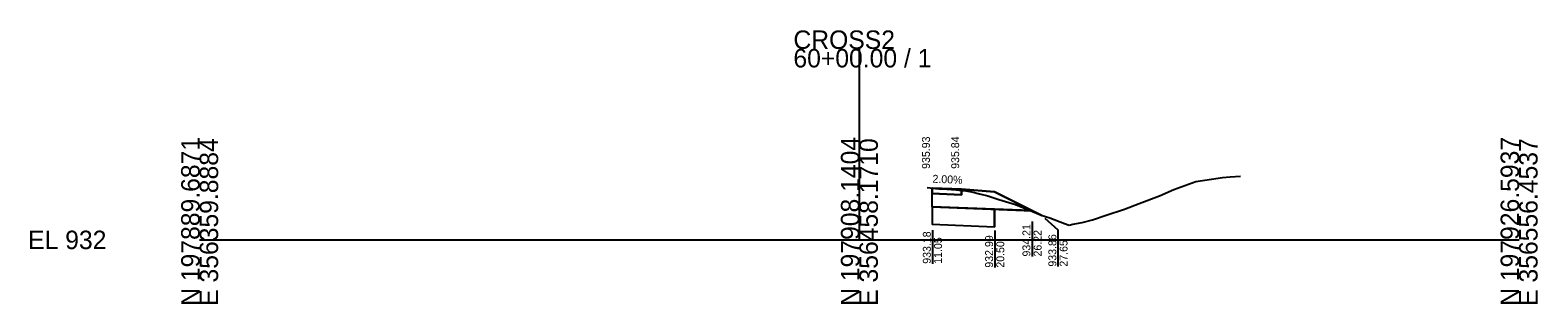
# Model space of a CAD drawing. Extents: x -26 to 203, y -10 to 14021.
# Drawn here: x -25.7 to 202.8, y 990.3 to 1031.8 of the extents above; entities that cross this region are included whole.
import ezdxf

# ---------------------------------------------------------------- set-up
doc = ezdxf.new("R2010")
doc.units = 0
for name, color, linetype in [('Default', 7, 'Continuous'), ('P_E_XS_Ground', 7, 'Continuous'), ('P_XS', 7, 'Continuous'), ('P_XS_EAR_CommonGrnd', 7, 'Continuous'), ('P_XS_Lane', 7, 'Continuous'), ('P_XS_Rock', 7, 'Continuous')]:
    doc.layers.add(name, color=color, linetype=linetype)

msp = doc.modelspace()

# ---------------------------------------------------------------- linework, layer by layer
at = {"layer": 'Default'}
for p, q in [((100, 1000), (100, 1028.94)), ((0, 1000), (100, 1000)), ((100, 1000), (200, 1000))]:
    msp.add_line(p, q, dxfattribs=at)
at = {"layer": 'P_E_XS_Ground'}
for p, q in [((110.28, 1007.95), (112.04, 1007.76)), ((147.68, 1007.65), (151, 1008.87)), ((151, 1008.87), (153.37, 1009.22)), ((153.37, 1009.22), (155.06, 1009.47)), ((155.06, 1009.47), (156.19, 1009.56)), ((156.19, 1009.56), (157.78, 1009.65)), ((112.04, 1007.76), (113.28, 1007.7)), ((113.28, 1007.7), (114.69, 1007.61)), ((114.69, 1007.61), (116.16, 1007.42)), ((116.16, 1007.42), (117.03, 1007.28)), ((117.03, 1007.28), (118.22, 1006.99)), ((118.22, 1006.99), (119.45, 1006.66)), ((119.45, 1006.66), (121.15, 1006.1)), ((121.15, 1006.1), (123.65, 1005.34)), ((142.39, 1005.53), (145.48, 1006.66)), ((145.48, 1006.66), (147.68, 1007.65)), ((123.65, 1005.34), (125.87, 1004.47)), ((125.87, 1004.47), (127.56, 1003.74)), ((127.56, 1003.74), (128.88, 1003.34)), ((128.88, 1003.34), (131.11, 1002.5)), ((135.33, 1003.05), (137.4, 1003.77)), ((137.4, 1003.77), (140.18, 1004.65)), ((140.18, 1004.65), (142.39, 1005.53)), ((131.11, 1002.5), (131.79, 1002.25)), ((131.79, 1002.25), (132.37, 1002.4)), ((132.37, 1002.4), (133.79, 1002.63)), ((133.79, 1002.63), (135.33, 1003.05))]:
    msp.add_line(p, q, dxfattribs=at)
at = {"layer": 'P_XS'}
for p, q in [((111.05, 1007.86), (111.05, 1007.03)), ((111.05, 1007.03), (115.5, 1006.85)), ((111.05, 1005.03), (111.05, 1007.03)), ((115.5, 1007.69), (115.5, 1006.85)), ((111.05, 1005.03), (126.22, 1004.42)), ((111.05, 1005.03), (111.05, 1002.36)), ((120.5, 1004.65), (120.5, 1001.98)), ((111.05, 1002.36), (120.5, 1001.98))]:
    msp.add_line(p, q, dxfattribs=at)
at = {"layer": 'P_XS_EAR_CommonGrnd'}
for points in [[(112.04, 1007.76), (113.28, 1007.7), (114.69, 1007.61), (115.5, 1007.5), (115.5, 1007.69), (111.05, 1007.86)], [(112.04, 1007.76), (113.28, 1007.7), (114.69, 1007.61), (115.5, 1007.5), (115.5, 1006.85), (111.05, 1007.03), (111.05, 1007.86)], [(125.87, 1004.47), (125.95, 1004.44), (120.5, 1004.65), (111.05, 1005.03), (111.05, 1007.03), (115.5, 1006.85), (115.5, 1007.5), (116.16, 1007.42), (117.03, 1007.28), (118.22, 1006.99), (119.45, 1006.66), (121.15, 1006.1), (123.65, 1005.34)], [(125.87, 1004.47), (125.95, 1004.44), (126.22, 1004.42), (120.5, 1007.29), (115.5, 1007.69), (115.5, 1007.5), (116.16, 1007.42), (117.03, 1007.28), (118.22, 1006.99), (119.45, 1006.66), (121.15, 1006.1), (123.65, 1005.34)], [(111.05, 1005.03), (111.05, 1002.36), (120.5, 1001.98), (120.5, 1004.65)], [(127.56, 1003.74), (127.65, 1003.71), (126.22, 1004.42), (125.95, 1004.44)]]:
    msp.add_lwpolyline(points, close=True, dxfattribs=at)
at = {"layer": 'P_XS_Lane'}
for p, q in [((111.05, 1007.86), (115.5, 1007.69)), ((115.5, 1007.69), (120.5, 1007.29)), ((120.5, 1007.29), (127.65, 1003.71))]:
    msp.add_line(p, q, dxfattribs=at)
at = {"layer": 'P_XS_Rock'}
for p, q in [((128.1, 1003.31), (130.1, 1001.54)), ((111.07, 1001.48), (111.07, 996.38)), ((120.51, 1001.4), (120.51, 995.79)), ((126.17, 1002.77), (126.17, 997.48)), ((130.1, 1001.54), (130.1, 995.95))]:
    msp.add_line(p, q, dxfattribs=at)

# ---------------------------------------------------------------- texts
at = {"layer": 'Default'}
for s, p in [('CROSS2', (90, 1028.94)), ('60+00.00 / 1', (90, 1026.14)), ('EL 932', (-26, 998.6))]:
    msp.add_text(s, height=2.8, dxfattribs=at).set_placement(p)
for s, p in [('N 197889.6871', (0, 990)), ('E 356359.8884', (2.8, 990)), ('N 197908.1404', (100, 990)), ('E 356458.1710', (102.8, 990)), ('N 197926.5937', (200, 990)), ('E 356556.4537', (202.8, 990))]:
    msp.add_text(s, height=2.8, rotation=90, dxfattribs=at).set_placement(p)
at = {"layer": 'P_XS_Rock'}
for s, rotation, p in [('935.93', 90, (110.69, 1010.76)), ('935.84', 90, (115.12, 1010.77)), ('2.00%', 357.7094, (111.06, 1008.67)), ('933.18', 90, (110.82, 996.38)), ('934.21', 90, (125.92, 997.48)), ('26.22', 90, (127.62, 997.48)), ('11.05', 90, (112.52, 996.38)), ('932.99', 90, (120.26, 995.79)), ('20.50', 90, (121.96, 995.79)), ('933.86', 90, (129.85, 995.95)), ('27.65', 90, (131.55, 995.95))]:
    msp.add_text(s, height=1.2, rotation=rotation, dxfattribs=at).set_placement(p)

doc.saveas('drawing.dxf')
